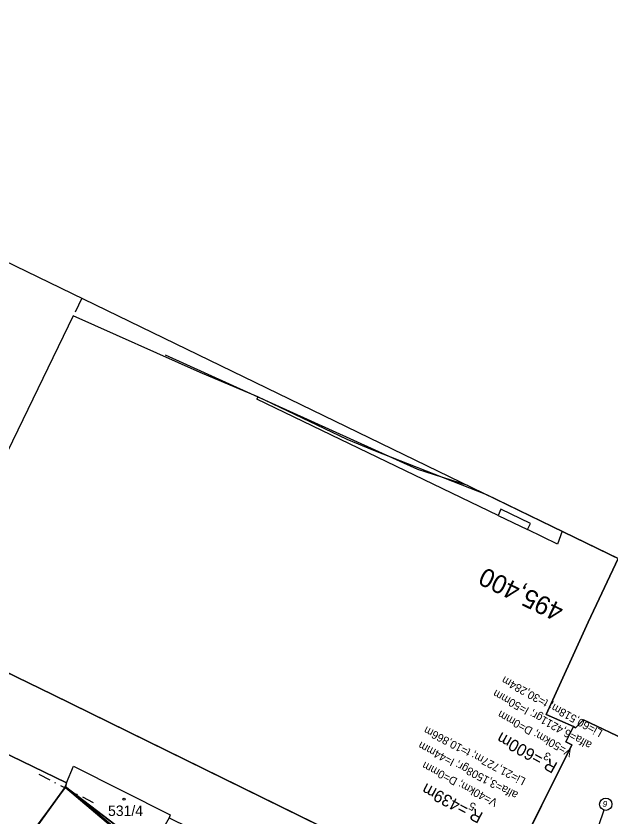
# Model space of a CAD drawing. Extents: x -762314 to -761449, y -993181 to -992589.
# Drawn here: x -762120.7 to -762024, y -992719.2 to -992589.1 of the extents above; entities that cross this region are included whole.
import ezdxf

# ---------------------------------------------------------------- set-up
doc = ezdxf.new("R2010")
doc.units = 0
for name, color, linetype in [('Formáty', 7, 'Continuous'), ('Hranice - vnitř_ kresba', 7, 'Continuous'), ('Hranice parcel', 7, 'Continuous'), ('Obvody jako plochy', 7, 'Continuous'), ('Parcelní čísla', 7, 'Continuous'), ('SO1010_lomy sklonů', 7, 'Continuous'), ('SO1010_osy_směrová a výšková úprava', 7, 'Continuous'), ('SO1010_podrobný popis další parametry', 7, 'Continuous'), ('SO1010_staničení a hektometry', 7, 'Continuous'), ('Telematika', 7, 'Continuous'), ('Vrstva 17', 7, 'Continuous'), ('Vrstva 23', 7, 'Continuous'), ('Vrstva 53', 7, 'Continuous'), ('Značky na budově v SPI', 7, 'Continuous')]:
    doc.layers.add(name, color=color, linetype=linetype)

msp = doc.modelspace()

# ---------------------------------------------------------------- linework, layer by layer
at = {"layer": 'Formáty'}
msp.add_line((-762110.01, -992634.95), (-762111.1, -992637.2), dxfattribs=at)
msp.add_lwpolyline([(-761558.02, -993180.94), (-762313.7, -992814.14), (-762204.47, -992589.1), (-761448.79, -992955.9)], close=True, dxfattribs=at)
msp.add_lwpolyline([(-761558.02, -993180.94), (-762313.7, -992814.14), (-762204.47, -992589.1), (-761448.79, -992955.9)], close=True, dxfattribs=at)
at = {"layer": 'Hranice - vnitř_ kresba'}
for p, q in [((-762081.42, -992650.99), (-762081.57, -992651.35)), ((-762042.39, -992670.23), (-762081.57, -992651.35)), ((-762041.92, -992669.24), (-762042.39, -992670.23)), ((-762042.39, -992670.23), (-762037.59, -992672.55)), ((-762037.12, -992671.56), (-762041.92, -992669.24)), ((-762037.59, -992672.55), (-762037.12, -992671.56)), ((-762032.71, -992674.9), (-762037.59, -992672.55)), ((-762031.98, -992672.82), (-762032.71, -992674.9))]:
    msp.add_line(p, q, dxfattribs=at)
at = {"layer": 'Hranice parcel'}
for p, q in [((-762090.79, -992647.02), (-762111.44, -992637.83)), ((-762081.42, -992650.99), (-762090.79, -992647.02)), ((-762066.92, -992657.88), (-762081.42, -992650.99)), ((-762062.56, -992659.67), (-762066.92, -992657.88)), ((-762044.23, -992666.88), (-762062.56, -992659.67)), ((-762027.73, -992687.58), (-762022.9, -992677.23)), ((-762027.73, -992687.58), (-762034.58, -992702.59)), ((-762136.24, -992688.91), (-762114.81, -992699.31)), ((-762112.54, -992713.71), (-762141.47, -992699.68)), ((-762114.81, -992699.31), (-762050.95, -992730.67)), ((-762030.15, -992704.54), (-762034.58, -992702.59)), ((-762028.49, -992703.45), (-762029.8, -992704.77)), ((-762013.47, -992710.58), (-762028.49, -992703.45)), ((-762031.38, -992707.03), (-762030.15, -992704.54)), ((-762029.8, -992704.77), (-762030.15, -992704.54)), ((-762043.7, -992734.26), (-762030.39, -992707.53)), ((-762030.39, -992707.53), (-762031.38, -992707.03)), ((-762112.54, -992713.71), (-762111.38, -992711)), ((-762111.38, -992711), (-762095.69, -992718.87)), ((-762112.67, -992714.34), (-762120.42, -992725)), ((-762112.54, -992713.71), (-762112.67, -992714.34)), ((-762103.03, -992722.33), (-762112.67, -992714.34)), ((-762112.67, -992714.34), (-762100.53, -992723.58)), ((-762095.69, -992718.87), (-762095.85, -992719.38))]:
    msp.add_line(p, q, dxfattribs=at)
at = {"layer": 'Obvody jako plochy'}
for p, q in [((-762111.44, -992637.83), (-762136.24, -992688.91)), ((-762022.9, -992677.23), (-762044.23, -992666.88)), ((-762112.54, -992713.71), (-762111.38, -992711)), ((-762111.38, -992711), (-762095.69, -992718.87)), ((-762112.54, -992713.71), (-762112.67, -992714.34)), ((-762112.67, -992714.34), (-762100.53, -992723.58)), ((-762103.03, -992722.33), (-762112.67, -992714.34)), ((-762112.67, -992714.34), (-762100.53, -992723.58)), ((-762095.69, -992718.87), (-762095.85, -992719.38))]:
    msp.add_line(p, q, dxfattribs=at)
for points in [[(-762044.23, -992666.88), (-762062.56, -992659.67), (-762066.92, -992657.88), (-762081.42, -992650.99), (-762090.79, -992647.02), (-762111.44, -992637.83)], [(-762136.24, -992688.91), (-762114.81, -992699.31), (-762050.95, -992730.67), (-762048.2, -992732.08), (-762044.87, -992733.64), (-762043.7, -992734.26), (-762030.39, -992707.53), (-762031.38, -992707.03), (-762030.15, -992704.54), (-762034.58, -992702.59), (-762027.73, -992687.58), (-762022.9, -992677.23)], [(-762022.9, -992677.23), (-762027.73, -992687.58), (-762034.58, -992702.59), (-762030.15, -992704.54), (-762029.8, -992704.77), (-762028.49, -992703.45), (-762013.47, -992710.58), (-762011.47, -992706.45), (-762009.13, -992707.58), (-762004.81, -992698.71), (-761997.86, -992702.08), (-761992.88, -992691.8)], [(-762141.47, -992699.68), (-762112.54, -992713.71), (-762111.38, -992711), (-762095.69, -992718.87), (-762095.85, -992719.38), (-762082.75, -992725.81), (-762082.3, -992724.77), (-762058.83, -992736.73), (-762053.67, -992739.48), (-762050.25, -992741.24), (-762051.34, -992743.38), (-762050.45, -992743.81), (-762048.6, -992734.17), (-762048.2, -992732.08), (-762050.95, -992730.67), (-762114.81, -992699.31), (-762136.24, -992688.91)], [(-762149.02, -992715.24), (-762146.45, -992716.39), (-762120.42, -992725), (-762112.67, -992714.34), (-762112.54, -992713.71), (-762141.47, -992699.68)]]:
    msp.add_lwpolyline(points, dxfattribs=at)
for points in [[(-762029.8, -992704.77), (-762030.15, -992704.54), (-762031.38, -992707.03), (-762030.39, -992707.53), (-762043.7, -992734.26), (-762018.87, -992745.84), (-761997.86, -992702.08), (-762004.81, -992698.71), (-762009.13, -992707.58), (-762011.47, -992706.45), (-762013.47, -992710.58), (-762028.49, -992703.45)], [(-762111.38, -992711), (-762095.69, -992718.87), (-762095.85, -992719.38), (-762096.94, -992721.27), (-762098.77, -992724.46), (-762100.53, -992723.58), (-762112.67, -992714.34), (-762112.54, -992713.71)], [(-762098.77, -992724.46), (-762100.53, -992723.58), (-762112.67, -992714.34), (-762112.54, -992713.71), (-762111.38, -992711), (-762095.69, -992718.87), (-762095.85, -992719.38), (-762096.94, -992721.27)], [(-762112.67, -992714.34), (-762100.53, -992723.58), (-762103.03, -992722.33)]]:
    msp.add_lwpolyline(points, close=True, dxfattribs=at)
at = {"layer": 'SO1010_lomy sklonů'}
msp.add_lwpolyline([(-762025.22, -992718.11), (-762039.53, -992760.32)], dxfattribs=at)
msp.add_circle((-762024.89, -992717.17), 1, dxfattribs=at)
at = {"layer": 'Telematika'}
msp.add_lwpolyline([(-762047.28, -992665.39), (-762055.45, -992662.77), (-762096.41, -992644.18)], dxfattribs=at)
at = {"layer": 'Vrstva 17'}
for p, q in [((-762117.03, -992712.27), (-762115.25, -992713.2)), ((-762114.46, -992713.62), (-762114.28, -992713.71)), ((-762113.48, -992714.12), (-762111.71, -992715.05)), ((-762110.91, -992715.47), (-762110.73, -992715.56)), ((-762109.94, -992715.98), (-762108.16, -992716.9))]:
    msp.add_line(p, q, dxfattribs=at)
at = {"layer": 'Vrstva 23'}
msp.add_lwpolyline([(-762103.05, -992722.54), (-762112.76, -992714.25)], dxfattribs=at)
at = {"layer": 'Vrstva 53'}
for p, q in [((-762120.49, -992724.94), (-762112.67, -992714.43)), ((-762112.67, -992714.43), (-762103.65, -992722.1))]:
    msp.add_line(p, q, dxfattribs=at)
at = {"layer": 'Značky na budově v SPI'}
msp.add_circle((-762103.17, -992716.33), 0.175, dxfattribs=at)

# ---------------------------------------------------------------- texts
at = {"layer": 'Parcelní čísla'}
msp.add_text('531/4', height=1.7, dxfattribs=at).set_placement((-762105.77, -992719.07))
at = {"layer": 'SO1010_lomy sklonů'}
msp.add_text('6', height=1, rotation=161.2351, dxfattribs=at).set_placement((-762024.5, -992716.77))
at = {"layer": 'SO1010_osy_směrová a výšková úprava'}
msp.add_text('495,400', height=3, rotation=154.1096, dxfattribs=at).set_placement((-762031.48, -992684.92))
at = {"layer": 'SO1010_podrobný popis další parametry'}
for s, height, rotation, p in [('Li=60,518m; t=30,284m', 1.3, 151.0554, (-762025.28, -992705.19)), ('alfa=6,4211gr; I=50mm', 1.3, 151.0554, (-762027.03, -992707.19)), ('V=50km; D=0mm', 1.3, 151.0554, (-762030.15, -992708.43)), ('Li=21,727m; t=10,866m', 1.3, 152.271, (-762037.78, -992713)), ('R =600m', 1.95, 151.0554, (-762032.57, -992710.53)), ('alfa=3,1508gr; I=44mm', 1.3, 152.271, (-762039.02, -992715.29)), ('3', 1.3, 151.0554, (-762033.69, -992709.07)), ('V=40km; D=0mm', 1.3, 152.271, (-762042.33, -992716.48)), ('R =439m', 1.95, 152.271, (-762044.68, -992718.64)), ('5', 1.3, 152.271, (-762045.87, -992717.18))]:
    msp.add_text(s, height=height, rotation=rotation, dxfattribs=at).set_placement(p)
at = {"layer": 'SO1010_staničení a hektometry'}
msp.add_text('495,400', height=3, rotation=154.1096, dxfattribs=at).set_placement((-762031.48, -992684.92))

doc.saveas('drawing.dxf')
